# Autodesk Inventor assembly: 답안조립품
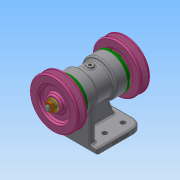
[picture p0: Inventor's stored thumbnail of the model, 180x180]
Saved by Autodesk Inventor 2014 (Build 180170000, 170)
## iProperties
Created: 2020-06
Part Number: 답안조립품
Document SubType Name: Assembly
Designer: net
Author: net
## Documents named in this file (12)
- C:\Users\net\Desktop\700606V1042\답안조립품.iam
- C:\Users\net\Desktop\700606V1042\답안본체.ipt
- C:\Users\net\Desktop\700606V1042\베어링 6204.ipt
- C:\Users\net\Desktop\700606V1042\축.ipt
- C:\Users\net\Desktop\700606V1042\키 5x5x12.ipt
- C:\Users\net\Desktop\700606V1042\V-벨트풀리.ipt
- C:\Users\net\Desktop\700606V1042\너트 M10.ipt
- C:\Users\net\Desktop\700606V1042\스프링 와셔 10.ipt
- C:\Users\net\Desktop\700606V1042\평면 와셔 10x21.ipt
- C:\Users\net\Desktop\700606V1042\오일 실 20 32 5.ipt
- C:\Users\net\Desktop\700606V1042\커버.ipt
- C:\Users\net\Desktop\700606V1042\볼트 M4.ipt
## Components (2 placed, 1 different names)
1. V-벨트풀리:1
2. V-벨트풀리:2
